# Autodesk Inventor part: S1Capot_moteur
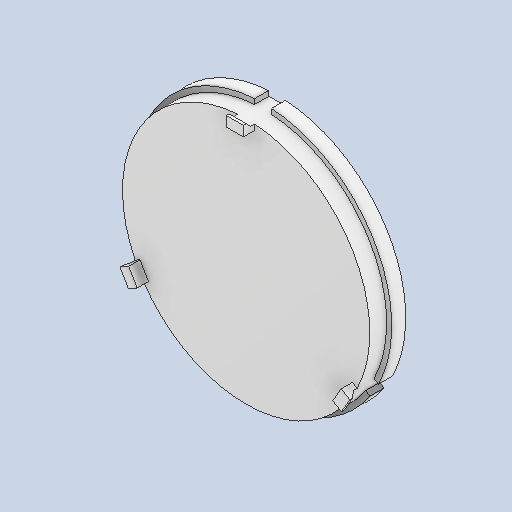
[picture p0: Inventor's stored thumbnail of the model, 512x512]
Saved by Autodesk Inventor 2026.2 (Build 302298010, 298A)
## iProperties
Created: 1601-01
Part Number: S1Capot_moteur
Material: ABS
Document SubType Name: Modeling
Designer: mel
Density: 1.02 g/cm^3
Appearance: white-pw-mt11050
Author: mel
Sending System: SOLIDWORKS 2023
Part Number: Capot_moteur
Last Saved Date: 2025-04-02
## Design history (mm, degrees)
feature "Enlèv. mat.-Extru.1"
node "Solide1"
